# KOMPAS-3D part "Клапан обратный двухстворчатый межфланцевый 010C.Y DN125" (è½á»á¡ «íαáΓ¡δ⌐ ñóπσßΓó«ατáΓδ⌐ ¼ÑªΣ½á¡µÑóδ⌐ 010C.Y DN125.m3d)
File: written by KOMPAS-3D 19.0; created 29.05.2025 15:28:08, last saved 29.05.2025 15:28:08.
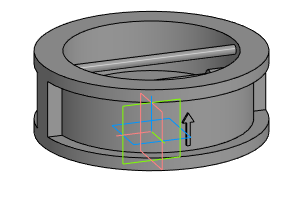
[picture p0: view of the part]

Document properties: Полное имя файла: E:\Dendor Работа Сачек\3D для проекитирвщиков\5.2 Тип 010C, 010C.Y Клапан обратный двухстворчатый межфланцевый\stp_Клапан обратный двухстворчатый межфланцевый 010C.Y\Клапан обратный двухстворчатый межфланцевый 010C.Y DN125.m3d

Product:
- Part/product: Клапан обратный двухстворчатый межфланцевый 010C.Y DN125

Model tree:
1. Операция без истории:1  (labels: Клапан обратный двухстворчатый межфланцевый 010C.Y DN125)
